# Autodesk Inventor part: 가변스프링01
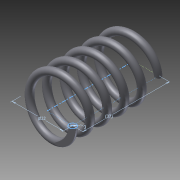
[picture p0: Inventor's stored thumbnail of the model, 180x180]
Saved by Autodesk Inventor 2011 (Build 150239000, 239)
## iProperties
Created: 2015-05
Part Number: 가변스프링01
Material: 탄소강
Document SubType Name: Modeling
Designer: Administrator
Mass: 18.8475 g
Surface Area: 32.4803 cm^2
Volume: 2.39485 cm^3
Density: 7.87 g/cm^3
Author: Administrator
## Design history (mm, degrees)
sketch "스케치1"
  geometry: L1 (0, 0)-(11, 0); L2 (11, 0)-(11, 37); L3 (11, 37)-(0, 37); L4 (0, 37)-(0, 0); C1 r 1.5 at (11, 0)
  constraints: 8 end point, 2 parallel, 1 centre point, 1 coincident, 1 horizontal, 1 perpendicular
  dimensions: "d0" = 3 diameter of C1; "d1" = 37 distance of L1.end L2.end (derived); "d2" = 22 diameter of L2 L4
feature "코일1" sketch "스케치1" pitch "d3" = 10; turns "d5" = 5; dims "d4" = 37 (= d1), "d6" = 0, angle "d7" = 90 deg, angle "d8" = 90 deg, "d9" = 0, "d10" = 0
sketch "스케치2"
  geometry: L1 (-12.5, 0)-(-9.5, 0) reference; 1 further point
  constraints: 1 horizontal alignment
extrude "돌출1" cut sketch "스케치2" stored distance "d11" = 10; taper "d12" = 0 deg
node "작업 평면1"
sketch "스케치3"
  geometry: L1 (3, 0)-(0, 0) reference; 1 further point
  constraints: 1 horizontal alignment
extrude "돌출2" cut sketch "스케치3" stored distance "d13" = 10; taper "d14" = 0 deg
node "솔리드1"
node "절단 모서리 투영1"
node "절단 모서리 투영2"
